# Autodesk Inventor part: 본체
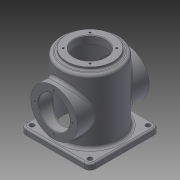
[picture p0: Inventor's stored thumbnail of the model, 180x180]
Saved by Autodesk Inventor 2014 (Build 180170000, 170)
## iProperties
Created: 2015-10
Part Number: 본체
Material: Generic
Document SubType Name: Modeling
Designer: 시험용
Density: 1 g/cm^3
Appearance: Default
Mass: 363.869 g
Surface Area: 1038.82 cm^2
Volume: 363.869 cm^3
Author: 시험용
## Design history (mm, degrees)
sketch "스케치1"
  geometry: L1 (-50, 60)-(50, 60); L2 (60, 50)-(60, -50); L3 (50, -60)-(-50, -60); L4 (-60, -50)-(-60, 50); C1 r 4 at (-50, 50); C2 r 4 at (-50, -50); C3 r 4 at (50, -50); C4 r 4 at (50, 50); A1 r 10 centre (-50, 50) between (-50, 60) and (-60, 50); A2 r 10 centre (50, 50) between (60, 50) and (50, 60); A3 r 10 centre (50, -50) between (50, -60) and (60, -50); A4 r 10 centre (-50, -50) between (-60, -50) and (-50, -60); 6 further points
  constraints: 8 centre point, 8 end point, 8 point on circle, 8 tangent, 6 equal radius, 6 point on line, 4 coincident, 2 midpoint, 2 parallel, 1 horizontal, 1 horizontal alignment, 1 perpendicular, 1 vertical alignment
  dimensions: "d0" = 120 distance of point (-60, 60) point (60, 60); "d1" = 120 distance of point (60, 60) point (60, -60); "d2" = 10 radius of A1; "d3" = 8 diameter of C2
extrude "돌출1" new body sketch "스케치1" distance "d4" = 10; taper "d5" = 0 deg
sketch "스케치2"
  geometry: C1 r 50 at (0, 0); 1 further point
  constraints: 1 centre point, 1 coincident
  dimensions: "d6" = 100 diameter of C1
extrude "돌출2" join sketch "스케치2" distance "d7" = 110; taper "d8" = 0 deg
sketch "스케치4"
  geometry: C1 r 45 at (0, 0); 1 further point
  constraints: 1 centre point, 1 coincident
  dimensions: "d12" = 90 diameter of C1
extrude "돌출4" cut sketch "스케치4" distance "d13" = 112; taper "d14" = 0 deg
sketch "스케치3"
  geometry: C1 r 40 at (0, 0); 1 further point
  constraints: 1 centre point, 1 coincident
  dimensions: "d9" = 80 diameter of C1
extrude "돌출3" join sketch "스케치3" distance "d10" = 5; taper "d11" = 0 deg
sketch "스케치5"
  geometry: C1 r 27 at (0, 0); 1 further point
  constraints: 1 centre point, 1 coincident
  dimensions: "d15" = 54 diameter of C1
extrude "돌출5" cut sketch "스케치5" stored distance "d16" = 112; taper "d17" = 0 deg
fillet "모깎기1" dims "d18" = 3
fillet "모깎기2" dims "d19" = 5
fillet "모깎기3" dims "d20" = 5
fillet "모깎기4" dims "d21" = 3
chamfer "모따기1" distance "d22" = 1; stored, may be unused: second distance "d23" = 2, angle "d24" = 45 deg
chamfer "모따기2" distance "d25" = 3; stored, may be unused: second distance "d26" = 2, angle "d27" = 45 deg
sketch "스케치6"
  geometry: L1 (0, 0)-(0, 32.5); L2 (0, 0)-(22.981, 22.981); A1 r 32.5 centre (0, 0) between (22.981, 22.981) and (0, 32.5); 4 further points
  constraints: 4 end point, 2 point on circle, 1 centre point, 1 coincident, 1 vertical, 5 other
  dimensions: "d28" = 65 diameter of A1; "d29" = 45 deg angle of L2 L1; "d32" = 360 deg dimension on point (0, 0) L2.end (derived)
hole "구멍1" sketch "스케치6" at (22.981, 22.981), (-22.981, 22.981), (-22.981, -22.981), (22.981, -22.981) diameter "d34" = 3.242; stored, may be unused: countersink angle "d38" = 90 deg, drill point angle "d40" = 118 deg; dims "d35" = 8, "d36" = 4, "d37" = 2, "d39" = 10
node "작업 평면2"
sketch "스케치7"
  geometry: L1 (50, -10)-(-50, -10) reference; C1 r 40 at (0, 50); 1 further point
  constraints: 1 centre point
  dimensions: "d42" = 60 distance from line of C1.centre L1; "d43" = 80 diameter of C1
extrude "돌출6" join sketch "스케치7" stored distance "d44" = 112; taper "d45" = 0 deg
fillet "모깎기5" dims "d46" = 5
sketch "스케치8"
  geometry: C1 r 40 at (0, 0) reference; A1 r 32.5 centre (0, 0) between (0, 32.5) and (-32.5, 0); 3 further points
  constraints: 4 point on circle, 2 horizontal alignment, 2 vertical alignment, 1 centre point, 1 coincident
  dimensions: "d47" = 65 diameter of A1
hole "구멍2" sketch "스케치8" at (0, 32.5), (-32.5, 0), (0, -32.5), (32.5, 0) diameter "d48" = 3.242; stored, may be unused: countersink angle "d52" = 90 deg, drill point angle "d54" = 118 deg; dims "d49" = 8, "d50" = 4, "d51" = 2, "d53" = 10
sketch "스케치9"
  geometry: C1 r 40 at (0, 0) reference; C2 r 27 at (0, 0); 1 further point
  constraints: 1 centre point, 1 coincident
  dimensions: "d55" = 54 diameter of C2
extrude "돌출7" cut sketch "스케치9" stored distance "d56" = 0; taper "d57" = 0 deg
chamfer "모따기3" distance "d58" = 1; stored, may be unused: second distance "d59" = 2, angle "d60" = 45 deg
fillet "모깎기6" dims "d61" = 3
node "작업 평면5"
sketch "스케치11"
  geometry: L1 (-5, 35)-(-5, 85); L2 (-5, 85)-(5, 85); L3 (5, 85)-(5, 35); L4 (5, 35)-(-5, 35); L5 (50, -10)-(-50, -10) reference; L6 (-5, 60)-(5, 60); 3 further points
  constraints: 4 midpoint, 2 end point, 1 vertical alignment, 2 other
  dimensions: "d66" = 70 distance between parallel lines of L5 L6; "d67" = 10 distance of L1.end L2.end; "d68" = 50 distance of L2.end L3.end
feature "엠보싱1" sketch "스케치11" dims "d0" = 120, "d1" = 120, "d2" = 10, "d3" = 8, "d8" = 0, "d69" = 0.5, "d70" = 0
node "솔리드1"
mirror "대칭1"
